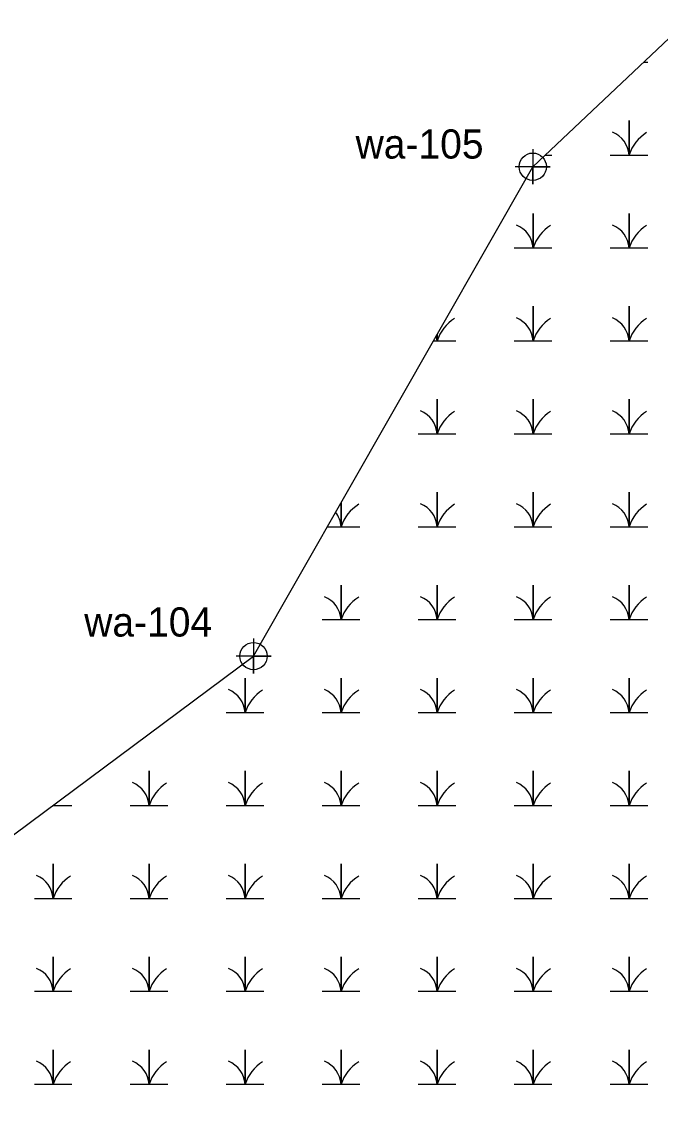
# Model space of a CAD drawing. Extents: x 2379288 to 2381905, y 330670 to 333511.
# Drawn here: x 2380484.3 to 2380593.7, y 332296.2 to 332483.8 of the extents above; entities that cross this region are included whole.
import ezdxf

# ---------------------------------------------------------------- set-up
doc = ezdxf.new("R2010")
doc.units = 0
for name, color, linetype in [('Exist Environmental Wetland Boundary', 7, 'Continuous'), ('Exist Environmental Wetland Boundary Cogo Number', 7, 'Continuous'), ('Exist Environmental Wetland Boundary Cogo Point CELL', 7, 'Continuous'), ('Exist Hydro Swamp or Marsh', 7, 'Continuous')]:
    doc.layers.add(name, color=color, linetype=linetype)

msp = doc.modelspace()

# ---------------------------------------------------------------- linework, layer by layer
at = {"layer": 'Exist Environmental Wetland Boundary'}
msp.add_lwpolyline([(2380442.38, 332045.91), (2380445.79, 332068.31), (2380430.27, 332144.34), (2380463.17, 332209.13), (2380440.55, 332246.83), (2380410.07, 332261.34), (2380400.64, 332277.99), (2380430.32, 332327.14), (2380475.22, 332338.88), (2380523.99, 332375.18), (2380571.84, 332459.01), (2380602.28, 332487.78), (2380643.42, 332522.54), (2380698.01, 332520.45), (2380758.16, 332538.88), (2380814.95, 332532.8), (2380827.75, 332553.62), (2380815.96, 332612.38), (2380841.18, 332668.4), (2380857.01, 332670.65), (2380837.85, 332627.97), (2380932.82, 332657.69)], dxfattribs=at)
at = {"layer": 'Exist Environmental Wetland Boundary Cogo Point CELL'}
for points in [[(2380571.84, 332462.01), (2380571.84, 332456.01), (2380571.84, 332459.01), (2380574.84, 332459.01), (2380568.84, 332459.01)], [(2380523.99, 332378.18), (2380523.99, 332372.18), (2380523.99, 332375.18), (2380526.99, 332375.18), (2380520.99, 332375.18)]]:
    msp.add_lwpolyline(points, dxfattribs=at)
for centre in [(2380571.84, 332459.01), (2380523.99, 332375.18)]:
    msp.add_circle(centre, 2.34, dxfattribs=at)
at = {"layer": 'Exist Hydro Swamp or Marsh'}
for p, q in [((2380590.8, 332476.93), (2380591.57, 332476.93)), ((2380573.96, 332461.01), (2380575.12, 332461.01))]:
    msp.add_line(p, q, dxfattribs=at)
for points in [[(2380585.12, 332461.01), (2380588.35, 332461.01), (2380588.35, 332466.93), (2380588.35, 332461.01), (2380591.57, 332461.01)], [(2380568.67, 332445.09), (2380571.9, 332445.09), (2380571.9, 332451.01), (2380571.9, 332445.09), (2380575.12, 332445.09)], [(2380585.12, 332445.09), (2380588.35, 332445.09), (2380588.35, 332451.01), (2380588.35, 332445.09), (2380591.57, 332445.09)], [(2380568.67, 332429.17), (2380571.9, 332429.17), (2380571.9, 332435.09), (2380571.9, 332429.17), (2380575.12, 332429.17)], [(2380585.12, 332429.17), (2380588.35, 332429.17), (2380588.35, 332435.09), (2380588.35, 332429.17), (2380591.57, 332429.17)], [(2380554.81, 332429.17), (2380555.45, 332429.17), (2380555.45, 332430.28)], [(2380555.45, 332430.28), (2380555.45, 332429.17), (2380558.67, 332429.17)], [(2380552.22, 332413.26), (2380555.45, 332413.26), (2380555.45, 332419.17), (2380555.45, 332413.26), (2380558.67, 332413.26)], [(2380568.67, 332413.26), (2380571.9, 332413.26), (2380571.9, 332419.17), (2380571.9, 332413.26), (2380575.12, 332413.26)], [(2380585.12, 332413.26), (2380588.35, 332413.26), (2380588.35, 332419.17), (2380588.35, 332413.26), (2380591.57, 332413.26)], [(2380552.22, 332397.34), (2380555.45, 332397.34), (2380555.45, 332403.26), (2380555.45, 332397.34), (2380558.67, 332397.34)], [(2380568.67, 332397.34), (2380571.9, 332397.34), (2380571.9, 332403.26), (2380571.9, 332397.34), (2380575.12, 332397.34)], [(2380585.12, 332397.34), (2380588.35, 332397.34), (2380588.35, 332403.26), (2380588.35, 332397.34), (2380591.57, 332397.34)], [(2380536.64, 332397.34), (2380538.99, 332397.34), (2380538.99, 332401.46)], [(2380538.99, 332401.46), (2380538.99, 332397.34), (2380542.22, 332397.34)], [(2380535.77, 332381.42), (2380538.99, 332381.42), (2380538.99, 332387.34), (2380538.99, 332381.42), (2380542.22, 332381.42)], [(2380552.22, 332381.42), (2380555.45, 332381.42), (2380555.45, 332387.34), (2380555.45, 332381.42), (2380558.67, 332381.42)], [(2380568.67, 332381.42), (2380571.9, 332381.42), (2380571.9, 332387.34), (2380571.9, 332381.42), (2380575.12, 332381.42)], [(2380585.12, 332381.42), (2380588.35, 332381.42), (2380588.35, 332387.34), (2380588.35, 332381.42), (2380591.57, 332381.42)], [(2380519.32, 332365.5), (2380522.54, 332365.5), (2380522.54, 332371.42), (2380522.54, 332365.5), (2380525.77, 332365.5)], [(2380535.77, 332365.5), (2380538.99, 332365.5), (2380538.99, 332371.42), (2380538.99, 332365.5), (2380542.22, 332365.5)], [(2380552.22, 332365.5), (2380555.45, 332365.5), (2380555.45, 332371.42), (2380555.45, 332365.5), (2380558.67, 332365.5)], [(2380568.67, 332365.5), (2380571.9, 332365.5), (2380571.9, 332371.42), (2380571.9, 332365.5), (2380575.12, 332365.5)], [(2380585.12, 332365.5), (2380588.35, 332365.5), (2380588.35, 332371.42), (2380588.35, 332365.5), (2380591.57, 332365.5)], [(2380502.87, 332349.59), (2380506.09, 332349.59), (2380506.09, 332355.5), (2380506.09, 332349.59), (2380509.32, 332349.59)], [(2380519.32, 332349.59), (2380522.54, 332349.59), (2380522.54, 332355.5), (2380522.54, 332349.59), (2380525.77, 332349.59)], [(2380535.77, 332349.59), (2380538.99, 332349.59), (2380538.99, 332355.5), (2380538.99, 332349.59), (2380542.22, 332349.59)], [(2380552.22, 332349.59), (2380555.45, 332349.59), (2380555.45, 332355.5), (2380555.45, 332349.59), (2380558.67, 332349.59)], [(2380568.67, 332349.59), (2380571.9, 332349.59), (2380571.9, 332355.5), (2380571.9, 332349.59), (2380575.12, 332349.59)], [(2380585.12, 332349.59), (2380588.35, 332349.59), (2380588.35, 332355.5), (2380588.35, 332349.59), (2380591.57, 332349.59)], [(2380489.6, 332349.59), (2380489.64, 332349.59), (2380489.64, 332349.62)], [(2380489.64, 332349.62), (2380489.64, 332349.59), (2380492.87, 332349.59)], [(2380486.42, 332333.67), (2380489.64, 332333.67), (2380489.64, 332339.59), (2380489.64, 332333.67), (2380492.87, 332333.67)], [(2380502.87, 332333.67), (2380506.09, 332333.67), (2380506.09, 332339.59), (2380506.09, 332333.67), (2380509.32, 332333.67)], [(2380519.32, 332333.67), (2380522.54, 332333.67), (2380522.54, 332339.59), (2380522.54, 332333.67), (2380525.77, 332333.67)], [(2380535.77, 332333.67), (2380538.99, 332333.67), (2380538.99, 332339.59), (2380538.99, 332333.67), (2380542.22, 332333.67)], [(2380552.22, 332333.67), (2380555.45, 332333.67), (2380555.45, 332339.59), (2380555.45, 332333.67), (2380558.67, 332333.67)], [(2380568.67, 332333.67), (2380571.9, 332333.67), (2380571.9, 332339.59), (2380571.9, 332333.67), (2380575.12, 332333.67)], [(2380585.12, 332333.67), (2380588.35, 332333.67), (2380588.35, 332339.59), (2380588.35, 332333.67), (2380591.57, 332333.67)], [(2380486.42, 332317.75), (2380489.64, 332317.75), (2380489.64, 332323.67), (2380489.64, 332317.75), (2380492.87, 332317.75)], [(2380502.87, 332317.75), (2380506.09, 332317.75), (2380506.09, 332323.67), (2380506.09, 332317.75), (2380509.32, 332317.75)], [(2380519.32, 332317.75), (2380522.54, 332317.75), (2380522.54, 332323.67), (2380522.54, 332317.75), (2380525.77, 332317.75)], [(2380535.77, 332317.75), (2380538.99, 332317.75), (2380538.99, 332323.67), (2380538.99, 332317.75), (2380542.22, 332317.75)], [(2380552.22, 332317.75), (2380555.45, 332317.75), (2380555.45, 332323.67), (2380555.45, 332317.75), (2380558.67, 332317.75)], [(2380568.67, 332317.75), (2380571.9, 332317.75), (2380571.9, 332323.67), (2380571.9, 332317.75), (2380575.12, 332317.75)], [(2380585.12, 332317.75), (2380588.35, 332317.75), (2380588.35, 332323.67), (2380588.35, 332317.75), (2380591.57, 332317.75)], [(2380486.42, 332301.83), (2380489.64, 332301.83), (2380489.64, 332307.75), (2380489.64, 332301.83), (2380492.87, 332301.83)], [(2380502.87, 332301.83), (2380506.09, 332301.83), (2380506.09, 332307.75), (2380506.09, 332301.83), (2380509.32, 332301.83)], [(2380519.32, 332301.83), (2380522.54, 332301.83), (2380522.54, 332307.75), (2380522.54, 332301.83), (2380525.77, 332301.83)], [(2380535.77, 332301.83), (2380538.99, 332301.83), (2380538.99, 332307.75), (2380538.99, 332301.83), (2380542.22, 332301.83)], [(2380552.22, 332301.83), (2380555.45, 332301.83), (2380555.45, 332307.75), (2380555.45, 332301.83), (2380558.67, 332301.83)], [(2380568.67, 332301.83), (2380571.9, 332301.83), (2380571.9, 332307.75), (2380571.9, 332301.83), (2380575.12, 332301.83)], [(2380585.12, 332301.83), (2380588.35, 332301.83), (2380588.35, 332307.75), (2380588.35, 332301.83), (2380591.57, 332301.83)]]:
    msp.add_lwpolyline(points, dxfattribs=at)
for centre, radius, start, end in [((2380583.75, 332460.68), 4.61, 4.1403, 67.535), ((2380595.19, 332458.74), 7.21, 122.1274, 161.6222), ((2380567.3, 332444.76), 4.61, 4.1403, 67.535), ((2380578.74, 332442.82), 7.21, 122.1274, 161.6222), ((2380583.75, 332444.76), 4.61, 4.1403, 67.535), ((2380595.19, 332442.82), 7.21, 122.1274, 161.6222), ((2380562.29, 332426.9), 7.21, 122.1274, 161.6222), ((2380567.3, 332428.84), 4.61, 4.1403, 67.535), ((2380578.74, 332426.9), 7.21, 122.1274, 161.6222), ((2380583.75, 332428.84), 4.61, 4.1403, 67.535), ((2380595.19, 332426.9), 7.21, 122.1274, 161.6222), ((2380550.85, 332428.84), 4.61, 4.1403, 14.9263), ((2380550.85, 332412.92), 4.61, 4.1403, 67.535), ((2380562.29, 332410.98), 7.21, 122.1274, 161.6222), ((2380567.3, 332412.92), 4.61, 4.1403, 67.535), ((2380578.74, 332410.98), 7.21, 122.1274, 161.6222), ((2380583.75, 332412.92), 4.61, 4.1403, 67.535), ((2380595.19, 332410.98), 7.21, 122.1274, 161.6222), ((2380545.84, 332395.07), 7.21, 122.1274, 161.6222), ((2380550.85, 332397.01), 4.61, 4.1403, 67.535), ((2380562.29, 332395.07), 7.21, 122.1274, 161.6222), ((2380567.3, 332397.01), 4.61, 4.1403, 67.535), ((2380578.74, 332395.07), 7.21, 122.1274, 161.6222), ((2380583.75, 332397.01), 4.61, 4.1403, 67.535), ((2380595.19, 332395.07), 7.21, 122.1274, 161.6222), ((2380534.39, 332397.01), 4.61, 4.1403, 37.4768), ((2380534.39, 332381.09), 4.61, 4.1403, 67.535), ((2380545.84, 332379.15), 7.21, 122.1274, 161.6222), ((2380550.85, 332381.09), 4.61, 4.1403, 67.535), ((2380562.29, 332379.15), 7.21, 122.1274, 161.6222), ((2380567.3, 332381.09), 4.61, 4.1403, 67.535), ((2380578.74, 332379.15), 7.21, 122.1274, 161.6222), ((2380583.75, 332381.09), 4.61, 4.1403, 67.535), ((2380595.19, 332379.15), 7.21, 122.1274, 161.6222), ((2380517.94, 332365.17), 4.61, 4.1403, 67.535), ((2380529.38, 332363.23), 7.21, 122.1274, 161.6222), ((2380534.39, 332365.17), 4.61, 4.1403, 67.535), ((2380545.84, 332363.23), 7.21, 122.1274, 161.6222), ((2380550.85, 332365.17), 4.61, 4.1403, 67.535), ((2380562.29, 332363.23), 7.21, 122.1274, 161.6222), ((2380567.3, 332365.17), 4.61, 4.1403, 67.535), ((2380578.74, 332363.23), 7.21, 122.1274, 161.6222), ((2380583.75, 332365.17), 4.61, 4.1403, 67.535), ((2380595.19, 332363.23), 7.21, 122.1274, 161.6222), ((2380501.49, 332349.25), 4.61, 4.1403, 67.535), ((2380512.93, 332347.31), 7.21, 122.1274, 161.6222), ((2380517.94, 332349.25), 4.61, 4.1403, 67.535), ((2380529.38, 332347.31), 7.21, 122.1274, 161.6222), ((2380534.39, 332349.25), 4.61, 4.1403, 67.535), ((2380545.84, 332347.31), 7.21, 122.1274, 161.6222), ((2380550.85, 332349.25), 4.61, 4.1403, 67.535), ((2380562.29, 332347.31), 7.21, 122.1274, 161.6222), ((2380567.3, 332349.25), 4.61, 4.1403, 67.535), ((2380578.74, 332347.31), 7.21, 122.1274, 161.6222), ((2380583.75, 332349.25), 4.61, 4.1403, 67.535), ((2380595.19, 332347.31), 7.21, 122.1274, 161.6222), ((2380496.48, 332347.31), 7.21, 161.2847, 161.6222), ((2380485.04, 332349.25), 4.61, 4.1403, 4.4966), ((2380485.04, 332333.33), 4.61, 4.1403, 67.535), ((2380496.48, 332331.39), 7.21, 122.1274, 161.6222), ((2380501.49, 332333.33), 4.61, 4.1403, 67.535), ((2380512.93, 332331.39), 7.21, 122.1274, 161.6222), ((2380517.94, 332333.33), 4.61, 4.1403, 67.535), ((2380529.38, 332331.39), 7.21, 122.1274, 161.6222), ((2380534.39, 332333.33), 4.61, 4.1403, 67.535), ((2380545.84, 332331.39), 7.21, 122.1274, 161.6222), ((2380550.85, 332333.33), 4.61, 4.1403, 67.535), ((2380562.29, 332331.39), 7.21, 122.1274, 161.6222), ((2380567.3, 332333.33), 4.61, 4.1403, 67.535), ((2380578.74, 332331.39), 7.21, 122.1274, 161.6222), ((2380583.75, 332333.33), 4.61, 4.1403, 67.535), ((2380595.19, 332331.39), 7.21, 122.1274, 161.6222), ((2380485.04, 332317.42), 4.61, 4.1403, 67.535), ((2380496.48, 332315.48), 7.21, 122.1274, 161.6222), ((2380501.49, 332317.42), 4.61, 4.1403, 67.535), ((2380512.93, 332315.48), 7.21, 122.1274, 161.6222), ((2380517.94, 332317.42), 4.61, 4.1403, 67.535), ((2380529.38, 332315.48), 7.21, 122.1274, 161.6222), ((2380534.39, 332317.42), 4.61, 4.1403, 67.535), ((2380545.84, 332315.48), 7.21, 122.1274, 161.6222), ((2380550.85, 332317.42), 4.61, 4.1403, 67.535), ((2380562.29, 332315.48), 7.21, 122.1274, 161.6222), ((2380567.3, 332317.42), 4.61, 4.1403, 67.535), ((2380578.74, 332315.48), 7.21, 122.1274, 161.6222), ((2380583.75, 332317.42), 4.61, 4.1403, 67.535), ((2380595.19, 332315.48), 7.21, 122.1274, 161.6222), ((2380485.04, 332301.5), 4.61, 4.1403, 67.535), ((2380496.48, 332299.56), 7.21, 122.1274, 161.6222), ((2380501.49, 332301.5), 4.61, 4.1403, 67.535), ((2380512.93, 332299.56), 7.21, 122.1274, 161.6222), ((2380517.94, 332301.5), 4.61, 4.1403, 67.535), ((2380529.38, 332299.56), 7.21, 122.1274, 161.6222), ((2380534.39, 332301.5), 4.61, 4.1403, 67.535), ((2380545.84, 332299.56), 7.21, 122.1274, 161.6222), ((2380550.85, 332301.5), 4.61, 4.1403, 67.535), ((2380562.29, 332299.56), 7.21, 122.1274, 161.6222), ((2380567.3, 332301.5), 4.61, 4.1403, 67.535), ((2380578.74, 332299.56), 7.21, 122.1274, 161.6222), ((2380583.75, 332301.5), 4.61, 4.1403, 67.535), ((2380595.19, 332299.56), 7.21, 122.1274, 161.6222)]:
    msp.add_arc(centre, radius, start, end, dxfattribs=at)

# ---------------------------------------------------------------- texts
at = {"layer": 'Exist Environmental Wetland Boundary Cogo Number'}
for s, p in [('wa-105', (2380541.48, 332460.4)), ('wa-104', (2380494.97, 332378.52))]:
    msp.add_text(s, height=5, dxfattribs=at).set_placement(p)

doc.saveas('drawing.dxf')
